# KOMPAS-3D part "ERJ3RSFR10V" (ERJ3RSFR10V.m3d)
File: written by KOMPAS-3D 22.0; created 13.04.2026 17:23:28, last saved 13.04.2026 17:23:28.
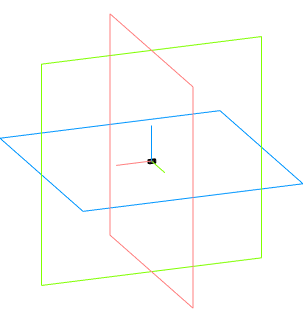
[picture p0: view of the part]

Document properties: Автор: Andrey; Полное имя файла: C:\Users\User1\Documents\ERJ3RSFR10V.m3d

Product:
- Part/product: ERJ3RSFR10V

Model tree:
1. Операция без истории:1
2. Операция без истории:2
3. Операция без истории:3
4. Операция без истории:4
